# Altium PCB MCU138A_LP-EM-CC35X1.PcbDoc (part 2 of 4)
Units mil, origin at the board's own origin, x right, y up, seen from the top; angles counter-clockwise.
Board outline 2309.44 x 2672.36 mil, 4 copper layers (Top Layer, L02_GND, L03_PWR, Bottom Layer), stack 60 mil thick; 235 components, 167 nets, 678 pads, 887 vias.
Unrouted connection lines stored in the file: 19.
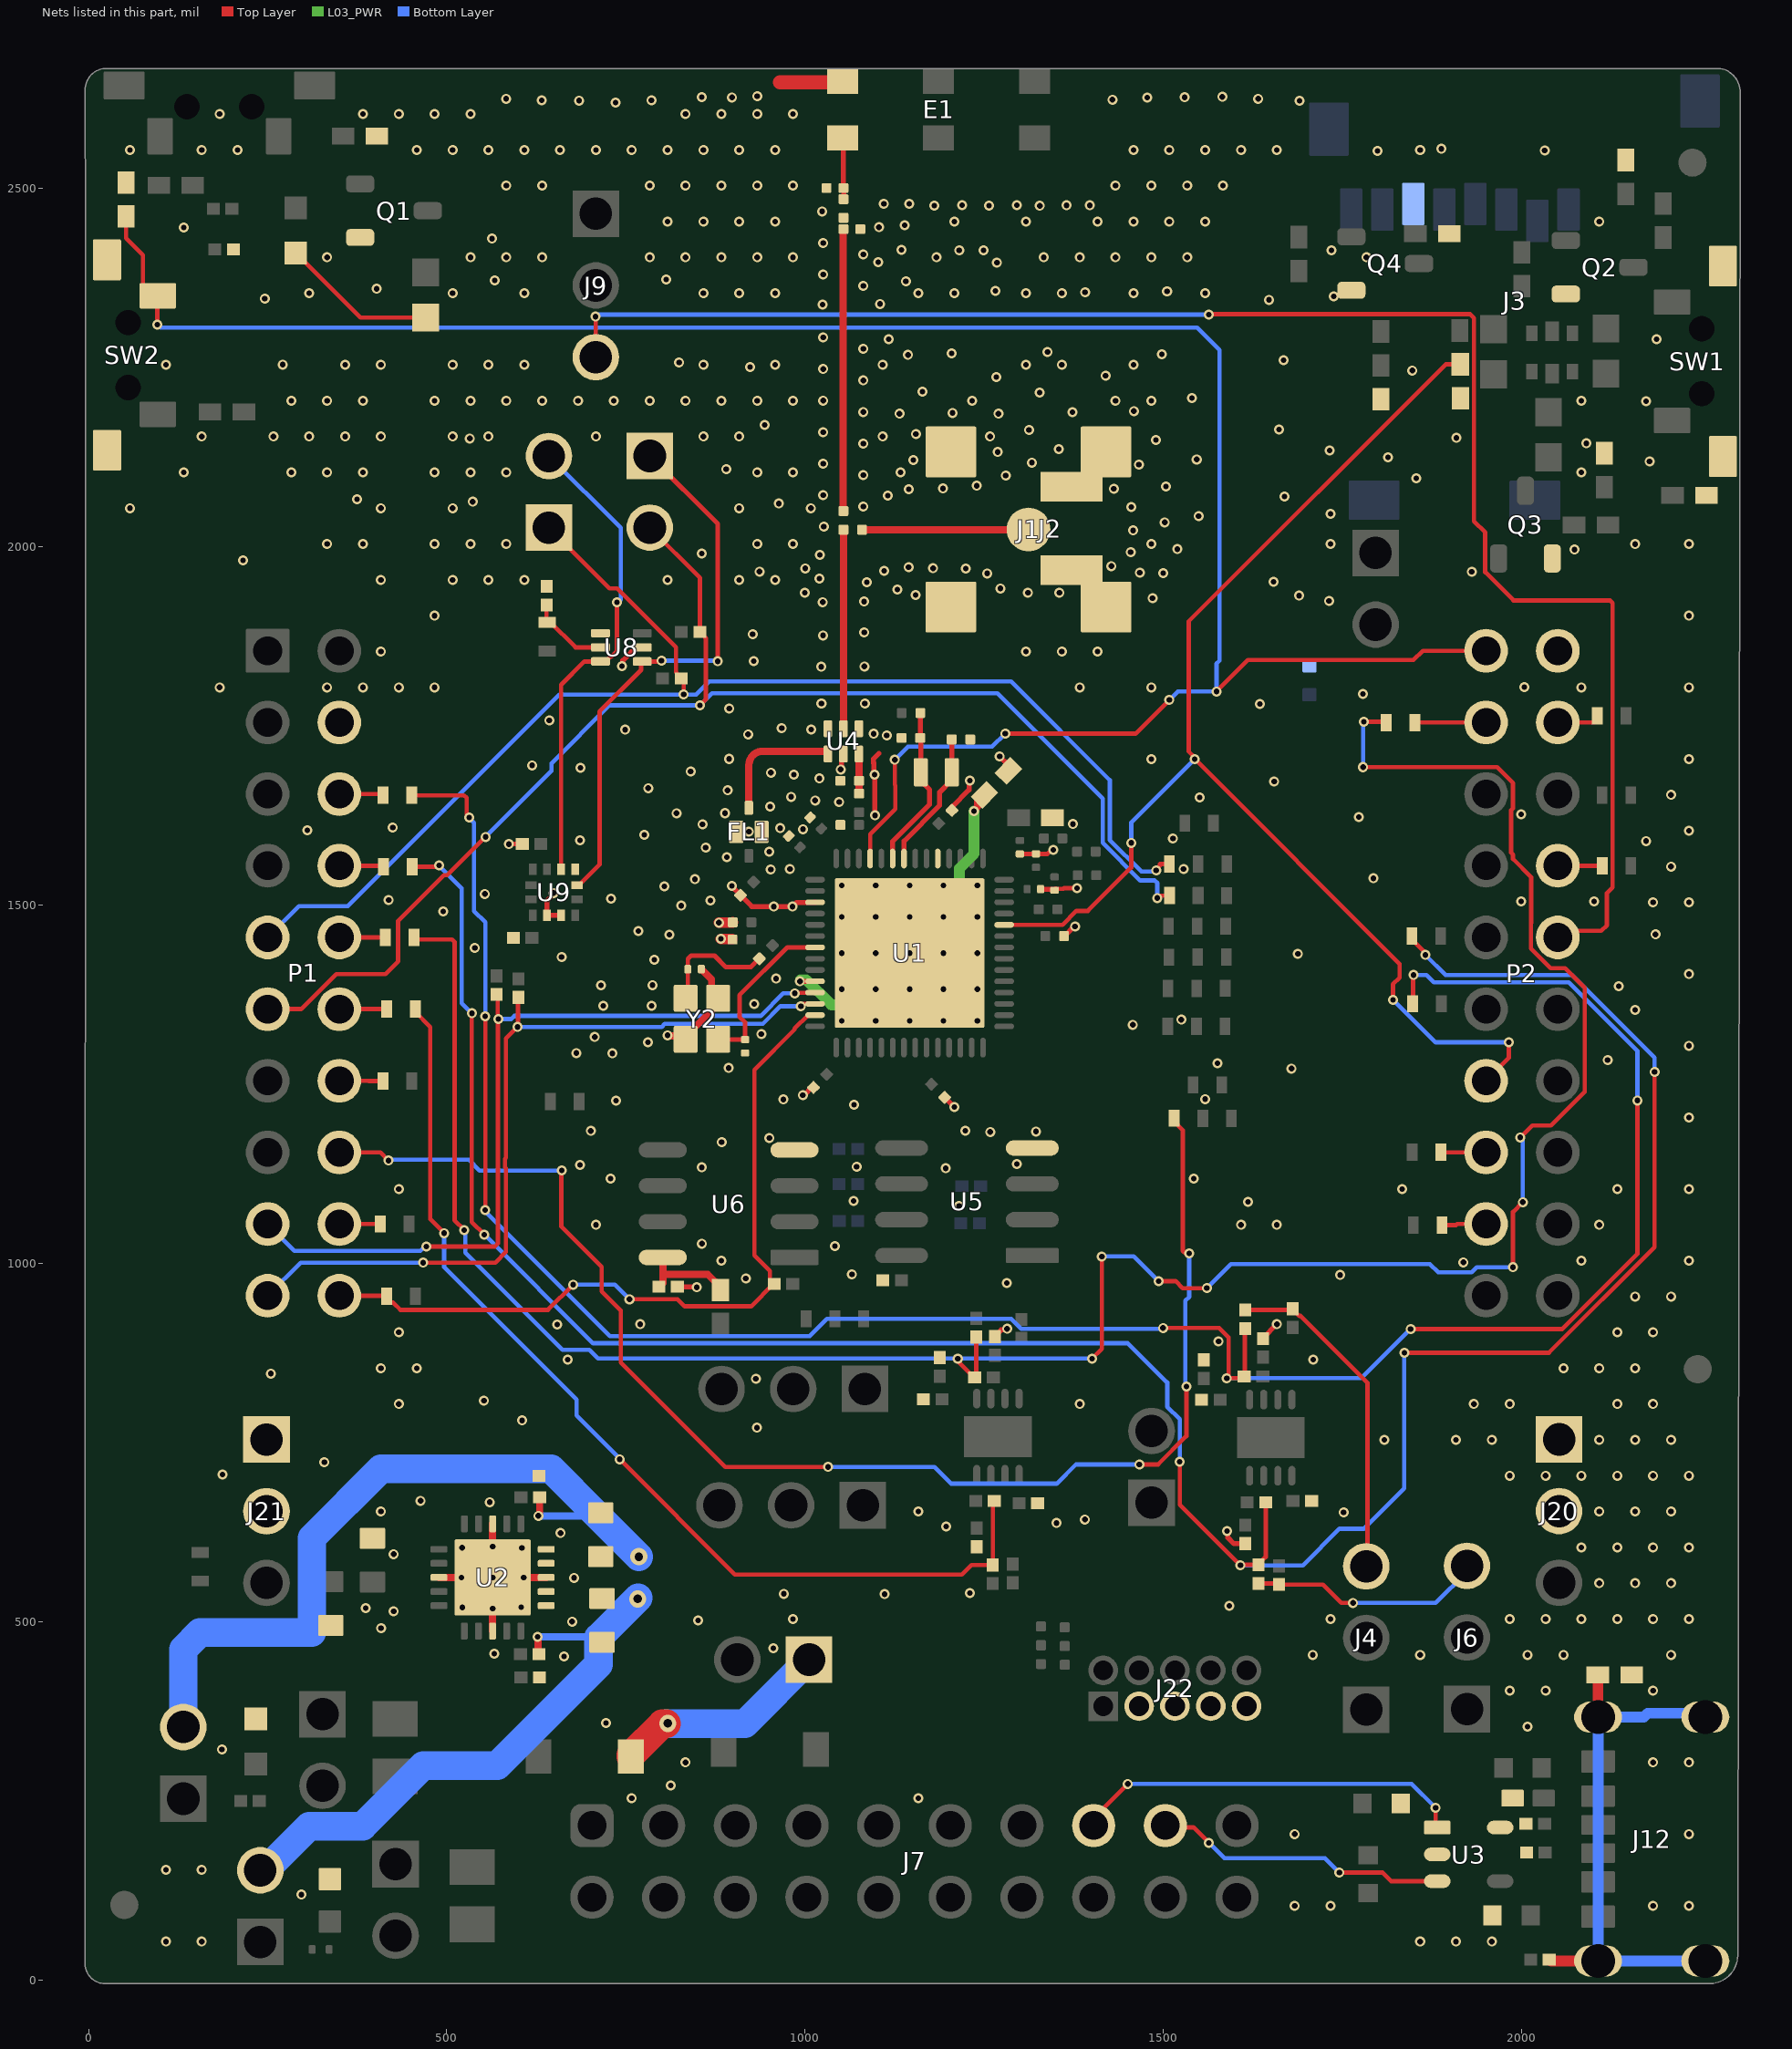
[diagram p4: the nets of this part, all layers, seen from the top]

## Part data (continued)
D1 D8: library part CMP-0028547-1, "Diode, Schottky, 30 V, 1 A, SOD-123", Manufacturer="ON Semiconductor", Supplier Part Number 1=MBR130T1GOSCT-ND, Value1=1A, Value2=0.47V
D2: "LED, Yellow, SMD", Alternate Manufacturer=Everlight, Alternate PartNumber=19-217/Y5C-AM1N1VY/3T, Color=yellow, Manufacturer="Wurth Elektronik", PartNumber=150060YS75000, Supplier Part Number 1=732-4981-1-ND, Value1=W, Value2=2V
D4: "LED, Rgb, SMD", Alternate Manufacturer=Everlight, Alternate PartNumber=19-337-R6GHBHC-C02-2T, Color=RGB, PartNumber=EAST1616RGBA8, Value1=W, Value2=3.7V
D5: library part CMP-0074747-2, "Diode, TVS, Bi, 5 V, SOD-523F", Manufacturer="ON Semiconductor", Value1=50W
D9: "LED, Green, SMD", Alternate Manufacturer=Everlight, Alternate PartNumber=19-217/GHC-YR1S2/3T, Color=Green, Manufacturer="Wurth Elektronik", PartNumber=150060GS75000, Supplier Part Number 1=732-4971-1-ND, Value1=W, Value2=3.2V
D10: library part CMP-0092006-1, "Red 630nm LED Indication - Discrete 1.5V 0603 (1608 Metric)", Color=Red, Digikey Part Number=2679-CTL0603FRD1TTR-ND, Forward Current=20mA, Manufacturer=Venkel, Operating Temperature Range="-40°C to +85°C", Power_TotalModule=60mW
E1: library part CMP-0001857-1, "WLAN ANTENNA 802.11, SMD", Alternate Manufacturer=----, Manufacturer=Ethertronics
FB1 FB2 FB3 FB4: library part CMP-0686-00587-3, "Chip Ferrite Bead, 0603, 470Ω @ 100MHz, 0.2Ω, 25%, 1A", Case Code (Imperial)=0603, Case Code (Metric)=1608, Current Rating=1A, DC Resistance (DCR)=200mR, Max Operating Temperature=125°C, Min Operating Temperature=-55°C, Package Quantity=1, Test Frequency=100MHz, Tolerance=25%
FID1 FID2 FID3: library part CMP-0077181-1, "Fiducial mark.  There is nothing to buy or mount.", Manufacturer=N/A
FL1: library part CMP-0091509-1, "2.45GHz Center Frequency Band Pass RF Filter (Radio Frequency) 100MHz Bandwidth 1.8dB 0603 (1608 Metric), 3 PC Pad", Digikey Part Number=445-175610-1-ND, Frequency_Fixed=2.45GHz, Manufacturer=TDK, Mouser Part Number=810-DEA162450BT1295A, Operating Temperature Range="-40°C to +85°C"
J1: library part CMP-0089646-1, "SMA Connector Jack, Female Socket 50Ohm Surface Mount Solder", Dielectric Material=PTFE, Digikey Part Number=931-1182-ND, Frequency_Fixed=0-12.4GHz, Manufacturer="Taoglas Limited", Mouser Part Number=960-PCB.SMAFST.J.BHT, Operating Temperature Range="-40°C to +85°C", Voltage_V=335V
J2: library part CMP-0075320-1, "Receptacle, Ultra Miniature Coaxial, Male Pin, 50 ohm, SMT", Alternate Manufacturer=----, Color=Beige, Manufacturer="Hirose Electric Co. Ltd.", Supplier Part Number 1=H122041-ND
J3: library part CMP-0078832-1, "MicroSD Card Connector, R/A, Gold, SMT", Color=Black, Current_A=5dA, Manufacturer="Wurth Elektronik", Supplier Part Number 1=732-3819-1-ND, Voltage_V=100V
J4 J6 J9 J10 J11 J20 J21: "Header, 2.54 mm, 3x1, Gold, TH", Alternate Manufacturer=----, Manufacturer="Wurth Elektronik", PartNumber=61300311121, Supplier Part Number 1=732-5316-ND
J5 J8 J13 J14 J15 J16 J17 J18: library part CMP-0054794-1, "Header, 2.54 mm, 2x1, Gold, TH", Manufacturer="Wurth Elektronik", Supplier Part Number 1=732-5315-ND
J7: library part CMP-0074634-1, "Receptacle, 2.54mm, 10x2, Gold, R/A, TH", Color=Black, Current_A=3A, Manufacturer="Sullins Connector Solutions", Supplier Part Number 1=S9205-ND, Voltage_V=1kV
J12: library part CMP-0094557-1, "24 (6+18 Dummy) Position USB-C (USB TYPE-C) USB 2.0 Receptacle Connector", Current_A=3A, Digikey Part Number=2073-USB4125-GF-A-0190CT-ND, Manufacturer=GCT, Mouser Part Number=640-USB4125-GF-A-190, Operating Temperature Range="-30°C to +85°C", Voltage_V=20V
J19: "Header, 2.54 mm, 2x1, Gold, TH", Alternate Manufacturer=----, Manufacturer="Wurth Elektronik", PartNumber=61300211121, Supplier Part Number 1=732-5315-ND
J22: "Header, 1.27 mm, 5x2, Gold, TH", Alternate Manufacturer=----, Color=Black, Manufacturer=Samtec, PartNumber=FTSH-105-01-F-D-K, Supplier Part Number 1=FTSH-105-01-F-D-K-ND
L1 L2: library part CMP-0090712-1, "3.9nH Unshielded Thick Film Inductor 500mA 170mOhm Max 0201 (0603 Metric)", Digikey Part Number=490-13933-1-ND, Manufacturer=Murata, Mouser Part Number=81-LQP03HQ3N9B02D, Operating Temperature Range="-55°C to +125°C", Self Resonant Frequency=7GHz, Test Frequency=500MHz, Tolerance_%=0.1nH
LBL1: library part CMP-0003625-1, "Thermal Transfer Printable Labels, 0.650\" W x 0.200\" H - 10,000 per roll", Manufacturer=Brady, Supplier Part Number 1=97C5133
LOGO1: library part CMP-0074844-1
Logo2 Logo8: library part CMP-0074838-1, "Texas Instrument Corporate Signature"
Logo3: library part CMP-0074847-1, "FCC_disclaimer"
Logo4: library part CMP-0074769-1
Logo5: library part CMP-0074840-1, "ESD Susceptible Symbol"
Logo7: library part CMP-0074846-1, "LaunchPad Rocket logo"
P1: library part CMP-0003837-2, "Receptacle, 2.54mm, 10x2, Tin, TH", Alternate Manufacturer="Major League Electronics", Alternate PartNumber=CRD-081413-A-G, Manufacturer=Samtec, Supplier Part Number 1=SAM1204-10-ND
P2: library part CMP-0078266-2, "Receptacle, 2.54mm, 10x2, Tin, TH", Alternate Manufacturer="Major League Electronics", Alternate PartNumber=CRD-081413-A-G, Manufacturer=Samtec, Supplier Part Number 1=SAM1204-10-ND
Q1 Q2 Q3 Q4: "MOSFET, N-CH, 50 V, 0.22 A, SOT-23", Alternate Manufacturer=ON, Alternate PartNumber=BSS138LT1G, Manufacturer="Fairchild Semiconductor", PartNumber=BSS138, Supplier Part Number 1=BSS138CT-ND, Value2="1.7 nC"
R1 R2 R3 R4: library part CMP-0078669-1, "RES, 10.0 k, 1%, 0.063 W, 0402", Manufacturer="Yageo America", Power_W=63mW, Supplier Part Number 1=311-10.0KLRCT-ND, TempCo="100 ppm/C", Tolerance_%=1%, Value2=0.063W, Value_Code=10k0, ValueDisplayed=10k
R5 R27 R41 R44 R50 R52 R56 R57 R58 R59 R60 R70 R71 R72 R73 R74 R75 R78 R79 R80 R81 R95 R96 R97 R98 R104 R105 R106 R107 R108: library part CMP-0027008-4, "RES, 0, 5%, 0.05 W, 0201", Manufacturer=Vishay-Dale, Power_W=50mW, Supplier Part Number 1=72M6743, TempCo=ppm/C, Tolerance_%=5%, Value2=0.05W, Value_Code=0000, ValueDisplayed=0
R6 R7 R9 R10 R11 R12 R13 R14 R15 R16 R17 R18 R19 R20 R21 R22 R23 R24 R25 R26 R28 R29 R30 R31 R32 R33 R34 R42 R43 R46 R61 R62 R66 R67 R82 R87 R88 R91 R99: "RES, 0, 5%, 0.063 W, 0402", Alternate Manufacturer=YAGEO, Alternate PartNumber=RC0402JR-070RL, Manufacturer=Panasonic, PartNumber=ERJ-2GE0R00X, Power_W=63mW, Supplier Part Number 1=P0.0JCT-ND, TempCo="600 ppm/C", Tolerance_%=5%, Value2=0.063W, Value_Code=0000, ValueDisplayed=0
R8 R83: "RES, 1.0 k, 5%, 0.063 W, AEC-Q200 Grade 0, 0402", Alternate Manufacturer=YAGEO, Alternate PartNumber=RC0402JR-071KL, Manufacturer=Vishay-Dale, PartNumber=CRCW04021K00JNED, Power_W=63mW, Supplier Part Number 1=541-1.0KJCT-ND, TempCo="200 ppm/C", Tolerance_%=5%, Value2=0.063W, Value_Code=1k00, ValueDisplayed=1.0k
R35: "RES, 750, 5%, 0.1 W, AEC-Q200 Grade 0, 0603", Alternate Manufacturer=YAGEO, Alternate PartNumber=RC0603JR-07750RL, Manufacturer=Vishay-Dale, PartNumber=CRCW0603750RJNEA, Power_W=100mW, Supplier Part Number 1=541-750GCT-ND, TempCo="200 ppm/C", Tolerance_%=5%, Value2=0.1W, Value_Code=750R, ValueDisplayed=750
R36: "RES, 100, 1%, 0.1 W, 0402", Alternate Manufacturer=----, Manufacturer=Panasonic, PartNumber=ERJ-2RKF1000X, Power_W=100mW, Supplier Part Number 1=P100LCT-ND, TempCo="100 ppm/C", Tolerance_%=1%, Value2=0.1W, Value_Code=100R, ValueDisplayed=100
R37: library part CMP-0027186-1, "RES, 10 k, 5%, 0.05 W, 0201", Manufacturer="Yageo America", Power_W=50mW, Supplier Part Number 1=603-RC0201JR-7D10KL, TempCo="200 ppm/C", Tolerance_%=5%, Value2=0.05W, Value_Code=10k0, ValueDisplayed=10k
R38 R89 R90: "RES, 10 k, 5%, 0.063 W, AEC-Q200 Grade 0, 0402", Alternate Manufacturer=YAGEO, Alternate PartNumber=RC0402JR-0710KL, Manufacturer=Vishay-Dale, PartNumber=CRCW040210K0JNED, Power_W=63mW, Supplier Part Number 1=541-10KJCT-ND, TempCo="200 ppm/C", Tolerance_%=5%, Value2=0.063W, Value_Code=10k0, ValueDisplayed=10k
R39: library part CMP-0027612-1, "RES, 33.2 k, 1%, 0.05 W, 0201", Manufacturer="Yageo America", Power_W=50mW, Supplier Part Number 1=YAG2607CT-ND, TempCo="200 ppm/C", Tolerance_%=1%, Value2=0.05W, Value_Code=33k2, ValueDisplayed=33.2k
R40: library part CMP-0027303-2, "RES, 10.7 k, 1%, 0.05 W, 0201", Manufacturer="Yageo America", Power_W=50mW, Supplier Part Number 1=311-10.7KMCT-ND, TempCo="200 ppm/C", Tolerance_%=1%, Value2=0.05W, Value_Code=10k7, ValueDisplayed=10.7k
R45: library part CMP-0027219-1, "RES, 2.0 k, 5%, 0.05 W, 0201", Manufacturer="Yageo America", Power_W=50mW, Supplier Part Number 1=603-RC0201JR-7D2KL, TempCo="200 ppm/C", Tolerance_%=5%, Value2=0.05W, Value_Code=2k00, ValueDisplayed=2.0k
R47 R48: library part CMP-0027789-1, "RES, 5.10 k, 1%, 0.05 W, 0201", Manufacturer="Yageo America", Power_W=50mW, Supplier Part Number 1=YAG2741CT-ND, TempCo="200 ppm/C", Tolerance_%=1%, Value2=0.05W, Value_Code=5k10, ValueDisplayed=5.10k
R49: library part CMP-0027957-1, "RES, 13.7 k, 1%, 0.05 W, 0201", Manufacturer="Yageo America", Power_W=50mW, Supplier Part Number 1=603-RC0201FR-7D13K7L, TempCo="200 ppm/C", Tolerance_%=1%, Value2=0.05W, Value_Code=13k7, ValueDisplayed=13.7k
R51: library part CMP-0027024-1, "RES, 11 k, 5%, 0.05 W, 0201", Manufacturer="Yageo America", Power_W=50mW, Supplier Part Number 1=311-11KNCT-ND, TempCo="200 ppm/C", Tolerance_%=5%, Value2=0.05W, Value_Code=11k0, ValueDisplayed=11k
R53: library part CMP-0097243-1, "49.9 Ohms ±1% 0.05W, 1/20W Chip Resistor 0201 (0603 Metric) Automotive AEC-Q200 Thick Film", Digikey Part Number=P123049CT-ND, Manufacturer="Panasonic Electronic Components", Mouser Part Number=667-ERJ-1GNF49R9C, Operating Temperature Range="-55°C to +125°C", Power_W=50mW, TempCo=200ppm/°C, Tolerance_%=1%
R54: library part CMP-0027960-1, "RES, 150, 1%, 0.05 W, 0201", Manufacturer="Yageo America", Power_W=50mW, Supplier Part Number 1=603-RC0201FR-7D150RL, TempCo="200 ppm/C", Tolerance_%=1%, Value2=0.05W, Value_Code=150R, ValueDisplayed=150
R55: library part CMP-0026822-3, "RES, 0, 5%, 0.063 W, AEC-Q200 Grade 0, 0402", Manufacturer=Vishay-Dale, Power_W=63mW, Supplier Part Number 1=541-0.0JCT-ND, TempCo="200 ppm/C", Tolerance_%=5%, Value2=0.063W, Value_Code=0000, ValueDisplayed=0
R63 R64: "RES, 0.1, 1%, 0.25 W, 0805", Alternate Manufacturer=----, Manufacturer=Bourns, PartNumber=CRM0805-FX-R100ELF, Power_W=250mW, Supplier Part Number 1=652-CRM0805FXR100ELF, TempCo="150 ppm/C", Tolerance_%=1%, Value2=0.25W, Value_Code=R100, ValueDisplayed=0.1
R65: library part CMP-0095637-1, "510 kOhms ±5% 0.1W, 1/10W Chip Resistor 0402 (1005 Metric) Automotive AEC-Q200 Thick Film", Digikey Part Number=P510KJCT-ND, Manufacturer=Panasonic, Mouser Part Number=667-ERJ-2GEJ514X, Operating Temperature Range="-55°C to +155°C", Power_W=100mW, TempCo=200ppm/°C, Tolerance_%=5%
R68 R69 R76 R77: library part CMP-0028132-1, "RES, 100 k, 0.5%, 0.05 W, 0201", Manufacturer="Yageo America", Power_W=50mW, Supplier Part Number 1=RC0201DR-07100KL-ND, TempCo="200 ppm/C", Tolerance_%=0.5%, Value2=0.05W, Value_Code=100k
R84 R85 R86: "RES, 750, 5%, 0.1 W, 0603", Alternate Manufacturer=----, Manufacturer="Yageo America", PartNumber=RC0603JR-07750RL, Power_W=100mW, Supplier Part Number 1=311-750GRCT-ND, TempCo="100 ppm/C", Tolerance_%=5%, Value2=0.1W, Value_Code=750R, ValueDisplayed=750
R92 R93 R94: "RES, 100 k, 5%, 0.063 W, AEC-Q200 Grade 0, 0402", Alternate Manufacturer=YAGEO, Alternate PartNumber=RC0402JR-07100KL, Manufacturer=Vishay-Dale, PartNumber=CRCW0402100KJNED, Power_W=63mW, Supplier Part Number 1=541-100KJCT-ND, TempCo="200 ppm/C", Tolerance_%=5%, Value2=0.063W, Value_Code=100k
R100 R101 R102 R103: library part CMP-0027564-1, "RES, 2.55 k, 1%, 0.05 W, 0201", Manufacturer="Yageo America", Power_W=50mW, Supplier Part Number 1=YAG2577CT-ND, TempCo="200 ppm/C", Tolerance_%=1%, Value2=0.05W, Value_Code=2k55, ValueDisplayed=2.55k
S1: library part CMP-0002328-1, "Switch, SPST, 0.05 A, 12 VDC, SMD", CurrentRating_mA=50A, Manufacturer=Diptronics
SH-J1 SH-J2 SH-J3 SH-J4 SH-J5 SH-J6 SH-J7 SH-J8 SH-J9 SH-J10 SH-J11 SH-J12 SH-J13 SH-J14: library part CMP-0003623-3, "Shunt, 100mil, Gold plated, Black", Alternate Manufacturer=3M, Alternate PartNumber=969102-0000-DA, Manufacturer=Samtec, PartNumber=SNT-100-BK-G, Supplier Part Number 1=SAM8858-ND
SW1 SW2: "Switch, SPST, 0.05 A, 12 VDC, SMD", Alternate Manufacturer=----, CurrentRating_mA=50A, Manufacturer=Diptronics, PartNumber=1188E-1K2-V-TR
U1: library part CMP-0121078-1, Manufacturer="Texas Instruments", Operating Temperature Range=to
U2: library part CMP-0073732-3, "Dual 1A Low-Noise (3.8μVRMS) LDO Voltage Regulator, RTJ0020D (WQFN-20)", Alternate Manufacturer="Texas Instruments", Alternate PartNumber=TPS7A8801RTJT, Operating Temperature Range="-40 to 125 C", Rating=Catalog
U3: library part CMP-0087170-1, "8KB I2C SER EEPROM TSOT 23", Manufacturer="ON Semiconductor"
U4: library part CMP-0091972-1, "Multilayer Diplexer For 2.4-2.5GHz W-LAN & Bluetooth / 5-7GHz W-LAN", Manufacturer=TDK, Operating Temperature Range="-40°C to +85°C"
U5: library part CMP-0120365-1, "FLASH - NOR Memory IC 64Mbit SPI - Quad I/O, QPI, DTR 133 MHz 6 ns 8-SOP", Digikey Part Number=706-IS25WJ032F-JNLE-ND, Frequency_Fixed=133MHz, Manufacturer=ISSI, Max Supply Voltage=2V, Min Supply Voltage=1.65V, Mouser Part Number=870-IS25WJ032F-JNLE, Nominal Supply Current=1.2-10mA, Operating Temperature Range="-40°C to +105°C", Part Number=IS25WJ032F-JNLE
U6: library part CMP-0121002-1, "DRAM IoT RAM 16Mb QSPI (x1,x4) SDR 144/84MHz, RBX, 1.8V, Ext. Temp., SOP8", Frequency_Fixed=144MHz, Manufacturer="AP Memory", Max Supply Voltage=1.98V, Min Supply Voltage=1.62V, Mouser Part Number=878-APS1604M-SQRX-SN, Nominal Supply Current=5-7mA, Operating Temperature Range="-40°C to +105°C"
U7 U10: library part CMP-0040617-1, "1.1 nV/rtHz Noise, Low Power, Precision Operational Amplifier, 4.5 to 36 V, -40 to 125 degC, 8-pin SON (DRG8), Green (RoHS & no Sb/Br)", Manufacturer="Texas Instruments", Rating=Catalog, Total Supply Voltage(Max)(+5V is 5, +/-5V is 10)=36, Total Supply Voltage(Min)(+5V is 5, +/-5V is 10)=4.5
U8: library part CMP-0092110-1, "Temperature Sensor With I 2C and SMBus Interface in Industry Standard LM75 Form Factor and Pinout", Manufacturer="Texas Instruments", Max Supply Voltage=5.5V, Min Supply Voltage=1.7V, Operating Supply Current=4-52uA, Operating Temperature Range="to +150°C"
U9: library part CMP-0004812-1, "14 Bit, Digital, Triaxial Acceleration Sensor with Intelligent On-Chip Motion-Triggered Interrupt Controller, 12LGA", Manufacturer="Bosch Solar Energy", Supplier Part Number 1=828-1033-1-ND
Y1: library part CMP-0001358-1, "Crystal Unit 1.6x1.0 Tuning Fork 32.768KHz", Frequency Stability=380ppm, Frequency Tolerance=20ppm, Frequency_Fixed=32.768kHz, Load Capacitance=7pF, Manufacturer="TAI-SAW Technology", Operating Temperature Range="-40°C to +125°C"
Y2: library part CMP-0123571-1, "Crystal Unit SMD 2.0x1.6 52.0MHz", Frequency Stability=-16/+18ppm, Frequency Tolerance=5ppm, Frequency_Fixed=52MHz, Load Capacitance=7pF, Manufacturer="TAI-SAW TECHNOLOGY", Operating Temperature Range="-40°C to +105°C"
ZZ1: library part CMP-0003616-3
ZZ2: library part CMP-0077236-1
ZZ3: library part CMP-0077237-1
ZZ4: library part CMP-0077238-1

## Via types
v1: diameter 14, hole 7.87, Top Layer to Bottom Layer, tented both sides, 816 vias
v2: diameter 19.68, hole 7.87, Top Layer to Bottom Layer, tented both sides, 25 vias
v3: diameter 14, hole 8, Top Layer to Bottom Layer, tented both sides, 19 vias
v4: diameter 24, hole 12, Top Layer to Bottom Layer, tented both sides, 14 vias
v5: diameter 19.68, hole 7.87, Top Layer to Bottom Layer, 13 vias

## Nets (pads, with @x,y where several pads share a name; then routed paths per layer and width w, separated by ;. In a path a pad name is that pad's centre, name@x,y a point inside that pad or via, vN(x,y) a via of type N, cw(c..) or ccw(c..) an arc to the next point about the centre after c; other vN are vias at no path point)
ADC2: P1.23 R7.2 | length 61.7
  Top Layer w6: P1.23@349.99,1654.89 409.3,1654.89 R7.2@411.02,1653.17
ADC3: P1.24 R10.2 | length 62.1
  Top Layer w6: P1.24@349.99,1554.89 410.2,1554.89 R10.2@411.54,1553.55
ADC4: P1.25 R12.2 | length 64.2
  Top Layer w6: P1.25@349.99,1454.89 413.98,1454.89 R12.2@414.15,1454.73
ADC5: P1.26 R15.2 | length 66.3
  Top Layer w6: P1.26@349.99,1354.89 416.01,1354.89 R15.2@416.19,1355.07
BoardID_SCA: J7.17 U3.3 | length 411.5
  Top Layer w6: J7.17@1502.5,215.64 1504.97,213.18 1541.62,213.18 v1(1563.3,191.5) ; v1(1745.32,149.98) 1805.63,149.98 1817.54,138.08 U3.3@1881.83,138.08
  Bottom Layer w6: v1(1563.3,191.5) 1584.82,169.98 1725.32,169.98 v1(1745.32,149.98)
BoardID_SCL: J7.15 U3.1 | length 549.5
  Top Layer w6: J7.15@1402.5,215.64 1402.5,226.09 v1(1450.14,273.74) ; v1(1879.53,240.42) 1879.53,215.18 U3.1@1881.83,212.88
  Bottom Layer w6: v1(1450.14,273.74) 1846.21,273.74 v1(1879.53,240.42)
COEX_GRANT: P2.40 R90.1 SW2.3 U1.53 | length 3188.8
  Top Layer w6: R90.1@52.45,2461.03 52.45,2430.73 76.07,2407.11 76.07,2364.87 90.79,2350.16 SW2.3@96.72,2350.16 96.18,2349.62 v1(96.18,2309.89) ; U1.53@1090.56,1564.97 1090.9,1565.3 1090.9,1599 1094.85,1602.96 1125.84,1633.94 1125.84,1666.79 1125.05,1667.58 v1(1125.05,1702.81) ; v1(1279.13,1739.24) 1461.07,1739.24 v1(1508.03,1786.2) ; v1(1573.92,1798.08) 1617.75,1841.9 1848.76,1841.9 1861.75,1854.89 P2.40@1949.99,1854.89
  Bottom Layer w6: v1(96.18,2309.89) 100.12,2305.95 1546.85,2305.95 1578.23,2274.58 1578.23,1841.08 1573.92,1836.77 v1(1573.92,1798.08) 1519.91,1798.08 v1(1508.03,1786.2) ; v1(1125.05,1702.81) 1143.26,1721.03 1260.91,1721.03 v1(1279.13,1739.24)
COEX_PRIOR: P2.39 R6.1 | length 99.6
  Top Layer w6: R6.1@1850.52,1754.59 1850.82,1754.89 P2.39@1949.99,1754.89
COEX_REQ: P2.19 R99.2 | length 61.5
  Top Layer w6: P2.19@2049.99,1754.89 2100.54,1754.89 2105.07,1759.43 R99.2@2105.07,1763.93
DCAN_TX: P2.32 R24.1 | length 62
  Top Layer w6: R24.1@1888.54,1053.55 1908.13,1053.55 1909.47,1054.89 P2.32@1949.99,1054.89
DIG_LDO_OUT: C23.2 U1.10 U1.47 | length 559.5
  Top Layer w7: v3@992.64,1393.71 U1.10@1013.79,1393.71
  Top Layer w10: v3(1235.58,1631.13) 1235.58,1632.21 1240.64,1637.27 1240.64,1648.14 1246.36,1653.86 C23.2@1250.11,1653.86
  L03_PWR w15: v3@993.78,1396.16 1001.02,1396.16 1036.4,1360.79 1202.44,1360.79 1215.24,1373.59 1215.24,1551.3 1235.58,1571.64 v3(1235.58,1631.13)
  other v3: 992.64,1393.61
Diplexer_A_IN: C11.1 C36.2 U4.6 | length 55.3
  Top Layer w10.25: U4.6@1074.94,1710.76 1075.03,1710.67 1075.03,1673.42 C36.2@1075.12,1673.33 C36.2@1075.12,1673.33 ; C36.2@1075.12,1673.33 C11.1@1075.15,1655.58 C11.1@1075.15,1655.58
Diplexer_BG_IN: FL1.3 U4.4 | length 182.5
  Top Layer w10.25: FL1.3@921.39,1635.72 921.39,1695.37 cw(c940.66,1695.37) 940.66,1714.64 1027.76,1714.64 U4.4@1031.63,1710.76
Diplexer_out: C8.1 C9.2 U4.2 | length 277.7
  Top Layer w10.25: U4.2@1053.29,1746.19 1053.29,2022.01 1053.38,2022.09 C9.2@1053.38,2023.85
GND: C1.2 C2.1 C3.1 C4.1 C5.1 C6.2 C7.2 C10.2 C12.2 C13.1 C14.1 C15.2 C16.2 C17.1 C18.2 C19.2 C20.1 C21.2 C22.2 C23.1 C24.2 C25.2 C26.1 C27.2 C28.1 C29.1 C30.1 C31.2 C32.2 C33.2 C34.2 C35.2 C36.1 C38.2 C40.2 C41.2 C42.2 D5.2 D9.1 D10.1 E1.1 E1.6 FB2.2 FB4.2 FL1.2 FL1.4 J1.2 J1.3 J1.4 J1.5 J2.2@1371.62,2083.61 J2.3@1371.62,1967.47 J3.6 J20.1 J20.2 J21.1 J21.2 J22.3 J22.5 J22.7 J22.9 L1.1 L2.1 L2.2 P1.22 P2.20 Q1.2 Q2.2 Q3.2 Q4.2 R3.2 R4.2 R36.2 R40.1 R47.1 R48.2 R51.1 R65.1 R68.1 R69.1 R76.1 R77.1 R80.1 R81.1 R89.2 R90.2 R92.2 R93.2 R94.2 SW1.1 SW1.2 SW2.1 SW2.2 U1.3 U1.57 U2.3 U2.8 U2.13 U2.18 U2.21 U3.2 U3.5 U4.1 U4.3 U4.5 U5.4 U6.4 U8.2 U8.4 U9.1 U9.8 U9.9 Y2.2 Y2.4 | length 1203.8
  Top Layer w6: v1(586.76,1585.12) 586.86,1585.22 C16.2@605.26,1585.22 ; C32.2@1299.55,1571.34 1299.61,1571.4 1321.96,1571.4 C12.2@1322.02,1571.46 1338.3,1571.46 1343.88,1577.04 v1(1346.05,1577.04) ; C31.2@1349.84,1522.6 1360.12,1522.6 1361.23,1523.72 v1(1379.25,1523.72)
  Top Layer w7: v1(648.92,1516.86) 648.92,1514.97 639.66,1505.71 U9.8@639.66,1485.84 U9.9@659.34,1485.84 ; v1(744.15,1833.57) 745.49,1834.91 745.49,1841.35 757.49,1853.35 759.08,1853.35 765.36,1859.63 U8.2@772.64,1859.63 ; C38.2@821.73,967.29 822.05,966.97 848.39,966.97 v1(848.71,966.66) ; v1@901.25,1522.2 925.44,1498 v3(956.29,1498) v3(982.28,1498) 988.05,1503.77 1013.62,1503.77 U1.3@1013.79,1503.94 ; v1(996.69,1234.93) 998.58,1234.93 1009.13,1245.48 C35.2@1011.62,1245.48 ; v3(1049.57,1689.25) 1050.91,1690.59 1050.91,1708.38 U4.5@1053.29,1710.76 ; E1.1@1052.13,2570.57 cw(c1049.15,2567.6) 1053.36,2567.6 L2.2@1053.36,2500.57 ; C10.2@1053.85,2488.35 L2.2@1053.85,2500.57 ; v3(1097.31,1625.21) 1097.11,1625.41 1097.11,1681.96 1095.58,1683.49 1095.58,1698.03 1095.26,1698.35 1095.26,1704.15 1102.68,1711.57 ; C33.2@1194.57,1231.63 v1(1208.01,1218.23) ; C22.2@1204.73,1632.29 1204.73,1637 1228.5,1660.76 1228.5,1672.46 v1(1229.84,1673.8) ; R68.1@1264.71,897.81 1264.71,898.6 1273.52,907.41 1280.39,907.41 v1(1281.72,908.75) ; v1(1271.4,1707.61) 1283.52,1695.48 C23.1@1283.52,1687.27 C23.1@1292.71,1687.27 ; C15.2@1327.67,1521.53 C15.2@1328.41,1522.27 1349.51,1522.27 C31.2@1349.84,1522.6 ; C34.2@1361.08,1456.88 1361.87,1456.88 1375.13,1470.14 v1(1376.42,1470.14) ; v1(1588.42,626.56) 1589.76,625.22 1589.76,617.37 1598.13,609 R77.1@1613.95,608.98 ; R69.1@1638.56,895.15 1638.56,895.93 1657.76,915.13 v1(1658.17,915.13)
  Top Layer w10: U2.3@489.08,561.81 v5(520.58,561.81) ; U2.8@563.88,487 v5(563.88,518.5) ; v5(563.88,605.11) U2.18@563.88,636.61 ; v5(607.19,561.81) U2.13@638.69,561.81 ; v3@808.33,1317.69 832.7,1317.69 836.27,1314.12 836.27,1319.67 881.54,1364.94 Y2.4@881.54,1368.82 ; C20.1@855.12,1409.68 855.95,1409.68 869.38,1396.25 869.38,1379.01 Y2.4@878.5,1369.89 ; J2.3@1363.66,1959.35 J2.3@1371.1,1966.79
  Top Layer w15: v3(879.55,1475.55) 898.55,1475.55 C24.2@898.94,1475.94 ; v3@882.51,1452.75 C25.2@897.89,1452.75
  Top Layer w20: 965.07,2648.17 E1.6@1045.57,2648.17
  other v1: 108.01,53.8 158.01,53.8 1858.01,53.8 1908.01,53.8 1958.01,53.8 1683.01,103.8 1733.01,103.8 2183.01,103.8 2233.01,103.8 297.26,119.28 108.01,153.8 158.01,153.8 1683.01,203.8 2233.01,203.8 758.01,253.8 1158.01,253.8 812.52,271.45 833.01,303.8 2183.01,303.8 2233.01,303.8 186.15,321.7 2008.01,353.8 721.88,358.83 1983.01,403.8 2033.01,403.8 2183.01,403.8 663.49,451.53 1708.01,453.8 1858.01,453.8 2008.01,453.8 2058.01,453.8 2208.01,453.8 566.14,455.57 955.47,462.97 408.21,490.89 674.69,500.2 850.7,501.72 983.01,503.8 1733.01,503.8 1983.01,503.8 2033.01,503.8 2083.01,503.8 2133.01,503.8 2183.01,503.8 2233.01,503.8 425.86,514.46 386.84,519.01 1591.86,522.23 970.32,539 1110.69,538.55 1229.91,539.9 2108.01,553.8 2158.01,553.8 2208.01,553.8 677.7,561.35 425.86,594.4 2083.01,603.8 2133.01,603.8 2183.01,603.8 2233.01,603.8 658.75,623.8 1196.73,632.87 1350.83,637.77 1390.35,642.7 1751.23,652.85 408.01,653.8 1158.01,653.8 2108.01,653.8 2158.01,653.8 2208.01,653.8 559.7,666.87 463.45,668.87 1983.01,703.8 2033.01,703.8 2083.01,703.8 2133.01,703.8 2183.01,703.8 2233.01,703.8 187.13,705.35 329.11,722.72 1808.01,753.8 1908.01,753.8 1958.01,753.8 2108.01,753.8 2158.01,753.8 2208.01,753.8 932.53,770.69 604.9,780.94 433.01,803.8 1383.01,803.8 1933.01,803.8 1983.01,803.8 2133.01,803.8 2183.01,803.8 551.78,808.52 931.18,839.08 254.55,846.31 408.01,853.8 458.01,853.8 2058.01,853.8 2108.01,853.8 2158.01,853.8 668.47,865.63 1708.82,865.63 1576.79,891.09 433.01,903.8 2133.01,903.8 2183.01,903.8 654.04,914.66 769.67,915.11 2158.01,953.8 2208.01,953.8 1281.3,972.76 917.15,979.2 1746.2,983.92 1065.21,984.64 1918.43,1001.6 883.01,1003.8 2083.01,1003.8 2233.01,1003.8 1041.53,1024.11 855.92,1027.64 708.01,1053.8 1608.01,1053.8 1658.01,1053.8 2108.01,1053.8 1214.81,1080.04 1617.85,1085.8 1067.34,1086.99 433.01,1103.8 1833.01,1103.8 2133.01,1103.8 2233.01,1103.8 728.46,1118.3 1542.04,1118.36 1196.06,1132.72 855.64,1134.06 1071.7,1134.78 685.93,1137.49 1295.3,1138.88 883.4,1169.17 950.15,1175.13 1258.1,1183.56 1322,1184.2 700.78,1184.95 1223.44,1185.25 2233.01,1203.8 1068.03,1221.34 735.89,1227.14 969.41,1228.77 1558.04,1229.3 1678.58,1271.97 893.23,1272.7 1575.11,1279.44 2119.54,1283.72 731.12,1293.02 680.57,1293.6 2233.01,1303.8 780.53,1308.53 706.42,1316 938.76,1320.18 1457.09,1332.98 1524.65,1340.15 2158.01,1353.8 718.43,1359.42 785.58,1359.42 928.93,1362.06 2134.88,1386.73 714.92,1388.18 786.81,1388.36 959.35,1397.4 2233.01,1403.8 789.34,1423.71 660.07,1427.47 1687.42,1432.13 539.1,1440.18 810.39,1458.69 2186.39,1459.05 767.12,1463.68 495.08,1491.19 826.86,1499.15 2183.01,1503.8 2233.01,1503.8 1999,1505.08 2100.91,1505.08 418.84,1507.27 729.17,1508.79 553.16,1515.57 803.67,1526.19 897.55,1526.82 846.03,1536.07 1792.67,1537.38 952.01,1549.78 978.67,1550.18 1527.83,1550.45 2208.01,1553.8 890.71,1566.92 949.88,1574.54 861.18,1580.06 2173.24,1589.46 685.66,1590.33 1513.11,1592.77 775.52,1598.02 921.47,1602.51 305.26,1604.25 2233.01,1603.8 996.85,1605.99 965.04,1607.28 424.54,1608.4 856.67,1612.5 1373.74,1613.01 1772.38,1622.98 1999,1626.71 820.48,1628.18 887.98,1628.27 951.3,1637.5 1047.38,1644.01 1013.85,1645.96 1550.55,1650.26 980.19,1651.06 2208.01,1653.8 891.66,1660.11 780.97,1663.15 1654.39,1672.61 1019.88,1676.64 984.22,1682.15 952.11,1684.79 840.2,1686.29 686.45,1691.38 619.03,1695.01 893.71,1703.97 1483.01,1703.8 2233.01,1703.8 1113.67,1736.92 920.27,1738.22 1095.64,1739.02 748.69,1744.8 1008.26,1744.88 967.25,1746.93 642.89,1757.77 894.14,1774.19 1022.68,1781.28 1083.24,1781.11 1634.54,1780.44 1778.23,1794.78 183.01,1803.8 333.01,1803.8 383.01,1803.8 433.01,1803.8 483.01,1803.8 1383.01,1803.8 1483.01,1803.8 2003.38,1804.24 2083.01,1803.8 2233.01,1803.8 1022.16,1832.57 1082.57,1833.05 928.04,1840.63 408.01,1853.8 1308.01,1853.8 1358.01,1853.8 1408.01,1853.8 1024.83,1876.35 926.69,1877.92 1082.48,1880.39 483.01,1903.8 2233.01,1903.8 1024.51,1922.71 1081.97,1923.55 1730.88,1924.33 1484.61,1928.08 1689.07,1931.79 1153.96,1932.71 999.33,1935.81 1310.81,1935.78 1354.74,1935.78 1128.41,1940.37 1272.49,1941.91 1085.83,1950.57 1653.59,1951.3 408.01,1953.8 508.01,1953.8 558.01,1953.8 608.01,1953.8 808.01,1953.8 908.01,1953.8 958.01,1953.8 1019.71,1955.76 1254.1,1962.86 1499.37,1963.16 1466.75,1964.03 936.18,1965.38 1929.97,1965.32 1110.02,1966.43 999.97,1969.86 1178.48,1970.01 1223.95,1969.5 1144.25,1971.54 1427.29,1973.07 215.49,1980.97 1020.65,1988.66 855.5,1990.47 1454.14,1992.3 2073.52,1996 1519.28,1996.74 333.01,2003.8 383.01,2003.8 483.01,2003.8 533.01,2003.8 583.01,2003.8 933.01,2003.8 983.01,2003.8 1483.01,2003.8 1733.01,2003.8 2157.9,2003.67 2233.01,2003.8 1457.65,2022.75 1025.9,2027.96 1501.63,2034.12 1548.87,2042.94 1732.89,2045.91 58.01,2053.8 408.01,2053.8 508.01,2053.8 908.01,2053.8 1008.01,2053.8 1081.17,2056.06 1455.01,2055.37 963.3,2060.3 536.05,2062.87 374.81,2066.4 1668.77,2069.95 1025.14,2071.95 1115.36,2071.53 1144.67,2080.27 1192.14,2081.25 1430.51,2080.98 1503.19,2083.95 1239.12,2085.16 1852.57,2095.69 1081.1,2100.06 1279.74,2099.36 133.01,2103.8 283.01,2103.8 333.01,2103.8 383.01,2103.8 483.01,2103.8 533.01,2103.8 583.01,2103.8 933.01,2103.8 983.01,2103.8 1133.01,2103.8 2083.01,2103.8 889.79,2108.11 1465.53,2114.75 1025.14,2115.95 1316.44,2117.46 2178.05,2119.11 1151.03,2120.89 1546.27,2121.84 1813.08,2124.72 1268.48,2132.14 1731.8,2134.22 1353.64,2136.19 1081.1,2144.06 2089.72,2144.31 1489.17,2148.84 532.1,2151.15 1908.77,2151.89 158.01,2153.8 258.01,2153.8 308.01,2153.8 358.01,2153.8 408.01,2153.8 508.01,2153.8 558.01,2153.8 708.01,2153.8 858.01,2153.8 908.01,2153.8 1108.01,2153.8 1258.01,2153.8 1154.46,2157.1 1025.14,2159.95 1312.16,2162.85 1661.27,2163.52 943.63,2170.13 1131.52,2185.69 1269.6,2185.69 1205.75,2186.73 1081.1,2188.06 1372.9,2187.77 1458.55,2189.33 2173.44,2203.09 283.01,2203.8 333.01,2203.8 383.01,2203.8 483.01,2203.8 533.01,2203.8 583.01,2203.8 633.01,2203.8 683.01,2203.8 733.01,2203.8 783.01,2203.8 833.01,2203.8 883.01,2203.8 933.01,2203.8 983.01,2203.8 1025.14,2203.95 1233.01,2203.8 1433.01,2203.8 1483.01,2203.8 2083.01,2203.8 1539.52,2207.49 1327.22,2215.28 1163.57,2216.33 1081.1,2232.06 1266.61,2236.68 1419.09,2238.64 1847.09,2245.94 1025.14,2247.95 923.3,2250.81 108.01,2253.8 271.08,2254.2 358.01,2253.8 408.01,2253.8 508.01,2253.8 558.01,2253.8 608.01,2253.8 858.01,2253.8 958.01,2253.8 1108.01,2253.8 1308.01,2253.8 1358.01,2253.8 1458.01,2253.8 824.14,2257.19 1667.32,2260.4 1143.46,2267.71 1497.48,2268.75 1204.28,2269.76 1338.12,2271.86 1081.1,2276.06 1116.35,2289.68 2188,2289.46 1025.14,2291.95 1024.35,2338.02 1104.5,2338.79 1647.24,2344.59 246,2346.4 1737.41,2349.33 308.01,2353.8 508.01,2353.8 608.01,2353.8 858.01,2353.8 908.01,2353.8 958.01,2353.8 1158.01,2353.8 1208.01,2353.8 1308.01,2353.8 1358.01,2353.8 1458.01,2353.8 1558.01,2353.8 1390.5,2355.13 1265.44,2356.99 1504.92,2356.36 401.93,2359.96 1081.1,2364.06 1140.44,2370.31 566.68,2371.49 806.01,2372.84 1025.14,2379.95 1101.96,2397.3 1267.51,2396.47 333.01,2403.8 533.01,2403.8 583.01,2403.8 633.01,2403.8 783.01,2403.8 833.01,2403.8 883.01,2403.8 933.01,2403.8 983.01,2403.8 1183.01,2403.8 1333.01,2403.8 1383.01,2403.8 1433.01,2403.8 1483.01,2403.8 1533.01,2403.8 1783.01,2403.8 1081.1,2408.06 1214.86,2413.84 1248.83,2413.84 1734.17,2413.71 1134.43,2414.32 1025.14,2423.95 563.13,2429.94 133.07,2445.65 1102.9,2445.83 1138.64,2448.72 808.01,2453.8 858.01,2453.8 908.01,2453.8 958.01,2453.8 1208.01,2453.8 1308.01,2453.8 1408.01,2453.8 1458.01,2453.8 1508.01,2453.8 1558.01,2453.8 2108.01,2453.8 1023.83,2467.93 1180.22,2476.06 1256.38,2476.06 1327.32,2475.69 1218.87,2476.45 1295.42,2476.45 1364.68,2476.34 1397.16,2476.34 1109.79,2478.36 1145,2478.74 583.01,2503.8 633.01,2503.8 783.01,2503.8 833.01,2503.8 883.01,2503.8 933.01,2503.8 983.01,2503.8 1433.01,2503.8 1483.01,2503.8 1533.01,2503.8 1583.01,2503.8 1798.71,2552.3 2031.7,2552.88 58.01,2553.8 158.01,2553.8 208.01,2553.8 458.01,2553.8 508.01,2553.8 558.01,2553.8 608.01,2553.8 658.01,2553.8 708.01,2553.8 758.01,2553.8 808.01,2553.8 858.01,2553.8 908.01,2553.8 958.01,2553.8 1458.01,2553.8 1508.01,2553.8 1558.01,2553.8 1608.01,2553.8 1658.01,2553.8 1858.01,2553.8 1887.69,2555.22 183.01,2603.8 383.01,2603.8 433.01,2603.8 483.01,2603.8 533.01,2603.8 833.01,2603.8 883.01,2603.8 933.01,2603.8 983.01,2603.8 735.49,2619.78 632.22,2622.87 684.5,2622.61 785.45,2622.87 1689.76,2622.39 1428.65,2623.91 582.78,2625.18 1632.12,2625.18 897.98,2626.99 1477.05,2626.9 1529.31,2627.12 855.75,2627.5 1582,2627.76 933.01,2628.53
  other v2: 1051.19,1338.59 1098.43,1338.59 1145.68,1338.59 1192.92,1338.59 1240.16,1338.59 1051.19,1382.68 1098.43,1382.68 1145.68,1382.68 1192.92,1382.68 1240.16,1382.68 1051.19,1433.08 1098.43,1433.08 1145.68,1433.08 1192.92,1433.08 1240.16,1433.08 1051.19,1483.47 1098.43,1483.47 1145.68,1483.47 1192.92,1483.47 1240.16,1483.47 1051.19,1527.56 1098.43,1527.56 1145.68,1527.56 1192.92,1527.56 1240.16,1527.56
  other v3: 807.94,1318.41 882.29,1452.97 867.67,1506.52 1096.92,1682.15
  other v5: 521.81,520.02 603.63,520.44 563.88,561.81 521.41,603.24 604.79,602.95
GPT0: P2.33 R21.1 | length 63.3
  Top Layer w6: R21.1@1886.84,1155.21 1887.15,1154.89 P2.33@1949.99,1154.89
GPT1: P2.17 R11.2 | length 62.2
  Top Layer w6: P2.17@2049.99,1554.89 2111.81,1554.89 R11.2@2112.06,1554.65
HFXT_N: C21.1 U1.7 Y2.3 | length 234.6
  Top Layer w6.17: Y2.3@879.7,1312.34 C21.1@916.2,1312.34 916.2,1336.38 908.43,1344.16 908.43,1374.23 975.15,1440.95 U1.7@1013.79,1440.95
HFXT_P: C20.2 R54.2 Y2.1 | length 166.8
  Top Layer w6.17: Y2.1@836.27,1371.21 836.27,1414.24 836.32,1414.3 836.32,1424.99 840.75,1429.42 873.5,1429.42 889.33,1413.59 924.42,1413.59 ; 924.07,1413.59 R54.2@935.73,1425.25
I2C0_CLK: P1.9 R102.1 U1.11 | length 1147
  Top Layer w6: v1(471.49,1023.56) 567.21,1023.56 571.18,1027.54 571.18,1340.18 v1(572.07,1341.07) 570.83,1342.31 570.83,1373.97 R102.1@569.59,1375.21 ; v1(985.46,1376.97) 986.1,1377.6 1013.43,1377.6 U1.11@1013.79,1377.96
  Bottom Layer w6: P1.9@249.99,1054.89 287.5,1017.38 463.14,1017.38 469.32,1023.56 v1(471.49,1023.56) ; v1(572.07,1341.07) 589.96,1341.07 594.32,1345.42 937.85,1345.42 969.4,1376.97 v1(985.46,1376.97)
I2C0_DATA: P1.10 R103.1 U1.12 | length 1150
  Top Layer w6: v1(467.05,1001.08) 567.71,1001.08 582.58,1015.94 582.58,1132.85 581.18,1134.25 581.18,1145.84 582.58,1147.24 582.58,1313.88 v1(598.64,1329.94) 599.42,1330.73 599.42,1370.34 R103.1@600.2,1371.12 ; v1(994.04,1358.9) 997.35,1362.21 U1.12@1013.79,1362.21
  Bottom Layer w6: P1.10@249.99,954.89 296.17,1001.08 v1(467.05,1001.08) ; v1(598.64,1329.94) 598.7,1330 799.73,1330 804.09,1334.35 940.93,1334.35 965.47,1358.9 v1(994.04,1358.9)
I2C1_CLK: J15.2 P1.6 R14.1 R100.1 | length 1933.1
  Top Layer w6: P1.6@249.99,1354.89 296.94,1354.89 345.86,1403.82 414.47,1403.82 432.02,1421.37 432.02,1477.92 495.74,1541.64 500.59,1541.64 v1(554.04,1595.09) ; J15.2@783.15,2026.76 853.25,1956.67 R100.1@853.25,1881.11 ; R100.1@853.01,1881.11 853.79,1881.11 859.06,1875.84 859.06,1874.76 861.5,1872.33 861.5,1787.05 v1(853.25,1778.8) ; v1(1491.29,1509.83) 1494.7,1513.24 R14.1@1508.38,1513.24
  Bottom Layer w6: v1(554.04,1595.09) 646.17,1687.22 646.17,1697.91 727.06,1778.8 v1(853.25,1778.8) 870.02,1795.58 1268.14,1795.58 1415.05,1648.67 1415.05,1586.78 1467.41,1534.42 1487.77,1534.42 1491.29,1530.9 v1(1491.29,1509.83)
I2C1_DATA: J18.1 P1.5 R66.1 R101.1 | length 1885
  Top Layer w6: J18.1@642.46,2026.58 727.01,1942.04 737.77,1942.04 819.84,1859.97 819.84,1824.95 821.02,1823.77 821.02,1821.44 826.29,1816.17 R101.1@827.08,1816.17 ; v1(830.52,1793.84) R101.1@830.52,1816.17 ; v1@1489.72,1550.58 1495.07,1555.93 1495.07,1557.28 R66.1@1508.18,1557.28
  Bottom Layer w6: P1.5@249.99,1454.89 293.75,1498.65 361.92,1498.65 657.11,1793.84 v1(830.52,1793.84) 847.98,1793.84 866.18,1812.04 1287.41,1812.04 1425.05,1674.4 1425.05,1590.92 1469.08,1546.89 1488.19,1546.89 v1(1489.72,1548.42)
I2C_CLK_SENS: J15.1 U8.1 U9.12 | length 783.5
  Top Layer w6.17: U9.12@681.59,1527.77 684.15,1527.77 713.01,1556.63 713.01,1770.17 771.24,1828.4 771.24,1838.54 U8.1@772.64,1839.94 798.17,1839.94 v1(799.49,1841.26) ; J15.1@783.15,2126.76 878.01,2031.9 v1(878.01,1840.24)
  Bottom Layer w6.17: v1(799.49,1841.26) 876.98,1841.26 v1(878.01,1840.24)
I2C_DATA_SENS: J18.2 U8.6 U9.2 | length 671.7
  Top Layer w6.17: U9.2@659.34,1550.01 659.34,1807.36 691.93,1839.94 U8.6@714.38,1839.94 721.66,1839.94 728.35,1846.64 729.36,1846.64 737.43,1854.71 v1(737.43,1922.58)
  Bottom Layer w6.17: J18.2@642.46,2126.58 742.75,2026.3 742.75,1926.2 739.13,1922.58 v1(737.43,1922.58)
I2S_BCLK/MCLK: P1.28 R20.2 | length 1972.8
  Top Layer w6: P1.28@349.99,1154.89 407.18,1154.89 v1(418.52,1143.55) ; v1(660.21,1129.62) 659.78,1129.19 659.78,1051.48 715.88,995.37 715.88,961.17 742.62,934.43 742.62,861.82 888.36,716.08 v1(1031.76,716.08) ; v1(1466.14,719.47) 1492.42,719.47 1531.9,758.95 v1(1531.9,828.2) ; R20.2@1514.83,1202.58 1514.83,1198.08 1526.79,1186.12 1526.79,1017.65 1532.01,1012.43 1533.78,1014.21 v1(1535.89,1014.21)
  Bottom Layer w6: v1(418.52,1143.55) 419.62,1144.64 530.77,1144.64 545.79,1129.62 v1(660.21,1129.62) ; v1(1031.76,716.08) 1180.32,716.08 1203.74,692.66 1350.97,692.66 1377.78,719.47 v1(1466.14,719.47) ; v1(1531.9,828.2) 1530.46,829.64 1530.46,948.03 1535.89,953.46 v1(1535.89,1014.21) v1@1537.42,1012.68
I2S_DATA0: P1.29 R23.2 | length 57.1
  Top Layer w6: P1.29@349.99,1054.89 407.01,1054.89 R23.2@407.09,1054.98
I2S_DATA1: P1.30 R26.2 R27.1 U1.13 | length 1084.3
  Top Layer w6: P1.30@349.99,954.89 415.52,954.89 R26.2@416.16,954.26 416.16,949.76 420.66,945.26 425.16,945.26 435.16,935.26 641.21,935.26 v1(676.29,970.34) ; v1(754.84,949.99) 821.86,949.99 831.66,940.19 924.41,940.19 R27.1@955.92,971.7 ; R27.1@956.7,971.7 R27.1@955.92,971.7 ; U1.13@1013.79,1346.46 1003.94,1346.46 985.24,1327.76 985.24,1326.38 929.04,1270.18 929.04,1011.3 950.65,989.7 950.65,976.97 R27.1@955.92,971.7
  Bottom Layer w6: v1(676.29,970.34) 734.49,970.34 v1(754.84,949.99)
I2S_WCLK: P1.27 R17.2 | length 61
  Top Layer w6: P1.27@349.99,1254.89 390.76,1254.89 391.03,1254.63 R17.2@410.89,1254.63
LFXT_N: C7.1 U1.50 Y1.2 | length 191.7
  Top Layer w7: U1.50@1137.72,1564.88 1137.89,1565.05 1137.89,1589.32 1187.73,1639.16 1187.73,1657.54 1203.83,1673.64 Y1.2@1203.83,1683.48 ; C7.1@1204.34,1731.05 1204.48,1730.91 Y1.2@1204.48,1685.39
LFXT_P: C6.1 R5.1 U1.51 Y1.1 | length 228.5
  Top Layer w7: U1.51@1122.05,1564.97 1122.05,1589.04 1173.58,1640.57 1173.58,1660.75 1161.14,1673.19 1160.61,1673.19 Y1.1@1160.61,1683.56 ; C6.1@1160.4,1733.28 1160.52,1733.4 1160.52,1768 R5.1@1160.64,1768.12 ; Y1.1@1161.18,1685.39 C6.1@1161.18,1733.28
LOGGER: P2.34 R1.2 R3.1 U1.38 | length 1833
  Top Layer w6: U1.38@1277.57,1472.45 1358.93,1472.45 1378.34,1491.86 1394.45,1491.86 1454.86,1552.26 v1(1454.86,1586.82) ; v1(1820.09,1367.94) 1820.09,1389.43 1829.29,1398.64 1829.29,1417.96 v1(1543.46,1703.79) 1543.46,1705.95 1535.15,1714.27 1535.15,1896.22 1893.52,2254.59 R3.1@1914.33,2254.59 ; P2.34@1949.99,1254.89 1981.62,1286.53 v1(1981.62,1308.46)
  Bottom Layer w6: v1(1454.86,1586.82) 1454.86,1615.18 v1(1543.46,1703.79) ; v1(1820.09,1367.94) 1879.57,1308.46 v1(1981.62,1308.46)
LP_GPIO3: R15.1 R74.1 R78.1 | length 1429
  Top Layer w6: R15.1@456.19,1355.07 456.19,1350.57 476.82,1329.94 476.82,1061.79 v1(496.34,1042.26) ; v1(741.22,726.7) 902,565.92 1218.65,565.92 1232.03,579.31 R78.1@1261.8,579.31 1261.8,666.22 R74.1@1263.88,668.3
  Bottom Layer w6: v1(496.34,1042.26) 496.34,994.46 680.94,809.86 680.94,787.86 741.22,727.58 v1(741.22,726.7)
LP_GPIO4: R6.2 R12.1 R50.1 R70.1 | length 3398.8
  Top Layer w6: R12.1@454.15,1454.73 454.15,1452.21 507.31,1452.21 510.83,1448.7 510.83,1060.14 v1(524.35,1046.61) ; v1(1212.9,867.22) 1214.43,865.69 1214.43,862.16 1235.64,840.95 R50.1@1236.43,840.95 R50.1@1238.73,843.26 ; R50.1@1236.43,843.28 1238.73,843.28 R70.1@1238.73,897.26 ; v1(1400.26,867.22) 1413.86,880.82 v1(1413.86,1009.76) ; v1(1493.06,975.33) 1516.88,975.33 1526.71,965.5 v1(1560.32,965.5) ; v1(1778.43,1692.53) 1965.41,1692.53 1987.5,1670.43 1987.5,1635.01 1985,1632.51 1985,1572.93 1987.5,1570.43 1987.5,1564.33 2013,1538.83 2013,1475.38 2012.47,1474.85 2012.47,1439.36 2039.81,1412.02 2060.16,1412.02 2087.5,1384.68 2087.5,1239.36 2040.6,1192.46 2014.36,1192.46 v1(1997.82,1175.93) ; v1(1779.38,1755.95) 1809.16,1755.95 R6.2@1810.52,1754.59 ; v1(1987.31,994.73) 1987.5,994.92 1987.5,1071.88 v1(2001.2,1085.57)
  Bottom Layer w6: v1(524.35,1046.61) 525.89,1045.08 525.89,1014.97 661.22,879.63 698.84,879.63 711.24,867.22 v1(1212.9,867.22) v1(1400.26,867.22) ; v1(1413.86,1009.76) 1458.63,1009.76 v1(1493.06,975.33) ; v1(1560.32,965.5) 1593.98,999.16 1871.67,999.16 1883.23,987.6 1929.64,987.6 1936.78,994.73 v1(1987.31,994.73) ; v1(1778.43,1692.53) 1778.43,1755.01 v1(1779.38,1755.95) ; v1(1997.82,1175.93) 2001.2,1172.56 v1(2001.2,1085.57)
LP_GPIO5: R10.1 R13.2 R75.1 R79.1 | length 3582.7
  Top Layer w6: R10.1@451.54,1553.55 487.31,1553.55 v1(489.05,1555.29) ; v1(534.85,1349.05) 534.85,1057.76 v1(552.36,1040.24) ; v1(1522.31,723.1) 1522.78,722.63 1522.78,663.21 v1(1607.31,578.68) 1608.12,579.49 R79.1@1632.36,579.49 1632.36,580.28 1642.52,590.44 R75.1@1642.52,666.76 ; v1(1835.87,875.44) 2037.72,875.44 2185.04,1022.76 v1(2185.04,1267.38) ; R13.2@1846.57,1456.82 1846.57,1452.32 1863.79,1435.1 1863.79,1431.95 v1(1865.32,1430.42)
  Bottom Layer w6: v1(489.05,1555.29) 520.8,1523.54 520.8,1363.09 v1(534.85,1349.05) ; v1(552.36,1040.24) 703.94,888.67 1450.34,888.67 1505.1,833.9 1505.1,800.22 1522.78,782.54 1522.78,723.58 v1(1522.31,723.1) ; v1(1607.31,578.68) 1694.25,578.68 1745.46,629.89 1779.8,629.89 1835.87,685.97 v1(1835.87,875.44) ; v1(1865.32,1430.42) 1893.34,1402.41 2069.67,1402.41 2185.04,1287.03 v1(2185.04,1267.38)
LP_GPIO5_Buf: J6.3 R73.2 R79.2 | length 329.3
  Top Layer w6: R79.2@1632.36,552.72 R79.2@1632.36,553.5 1659.74,553.5 R73.2@1661.27,551.98 1722.51,551.98 1748.18,526.31 v1(1764.42,526.31)
  Bottom Layer w6: v1(1764.42,526.31) 1879.81,526.31 1923.3,569.8 J6.3@1923.3,578.12
LP_GPIO6: R7.1 R18.2 R52.1 R71.1 | length 3274.3
  Top Layer w6: R7.1@451.02,1653.17 524.08,1653.17 527.59,1649.66 527.59,1625.79 v1(531.22,1622.17) ; v1(553.68,1074.4) v1(553.68,1345.01) ; v1(1499.31,909.98) 1577.7,909.98 1590.79,896.89 1590.79,844.55 1588.26,842.02 v1(1588.26,839.86) 1610.13,839.86 R52.1@1612.48,842.21 1613.32,843.04 1613.32,908.7 R71.1@1613.79,909.18 ; v1@1845.74,909.63 v1(1844.65,908.54) 2056.68,908.54 2161.08,1012.94 v1(2161.08,1227.39) ; R18.2@1847.6,1362.41 1848.14,1362.95 1848.14,1401.99 v1(1848.69,1402.54)
  Bottom Layer w6: v1(531.22,1622.17) 531.22,1621.49 538.05,1614.65 538.05,1491.55 553.68,1475.93 v1(553.68,1345.01) ; v1(553.68,1074.4) 553.68,1072.49 727.49,898.67 1006.39,898.67 1030.47,922.75 1287.52,922.75 1301.49,908.78 1498.11,908.78 v1(1499.31,909.98) ; v1(1588.26,839.86) 1775.97,839.86 v1(1844.65,908.54) ; v1(1848.69,1402.54) 1867.03,1402.54 1877.15,1392.41 2065.52,1392.41 2161.08,1296.85 v1(2161.08,1227.39)
LP_GPIO6_Buf: J4.3 R44.2 R71.2 | length 479.7
  Top Layer w6: R71.2@1608.52,929.11 1613.79,934.38 R71.2@1613.79,935.16 1678.58,935.16 R44.2@1680.17,936.75 1680.17,935.96 1689.31,926.82 1691.33,926.82 1784.48,833.67 1784.48,579.06 J4.3@1782.8,577.38
LP_RESET: J9.3 P2.16 | length 2371.4
  Top Layer w6: v1(707.37,2321.16) 707.67,2320.87 707.67,2264.94 J9.3@707.96,2264.64 ; v1(1563.05,2323.91) 1563.65,2324.52 1841.61,2324.52 1927.8,2324.52 1933.14,2319.17 1933.14,2035.5 1948.73,2019.92 1948.73,1964.59 1988.14,1925.18 2122.96,1925.18 2126.48,1921.67 2126.48,1569.63 2126.56,1569.55 2126.56,1524.74 2118.59,1516.76 2118.59,1471.96 2110.69,1464.07 2059.16,1464.07 P2.16@2049.99,1454.89
  Bottom Layer w6: v1(707.37,2321.16) 710.11,2323.91 v1(1563.05,2323.91)
NetC4_2: C4.2 J13.2 R39.2 U2.14 U2.15 | length 1084.1
  Top Layer w10: v1(627.64,647.77) 627.64,648.86 629.49,650.7 R39.2@629.49,673.93
  Bottom Layer w10: v1(627.64,647.77) 702.33,647.77 706.6,652.04
  Bottom Layer w40: J13.2@132.3,353.09 132.3,461.52 155.74,484.95 311.7,484.95 311.7,617.06 407.96,713.32 645.32,713.32 706.6,652.04 v4(767.87,590.77)
NetC5_2: C5.2 J14.2 R49.2 U2.11 U2.12 | length 816.9
  Top Layer w10: v1(626.61,478.94) 627.38,478.17 627.38,455.94 R49.2@628.68,454.64
  Bottom Layer w10: v1(626.61,478.94) 710.22,478.94 711.4,477.76
  Bottom Layer w40: J14.2@239.78,153.23 246.53,153.23 307.94,214.63 382.4,214.63 466.98,299.2 570.2,299.2 711.4,440.41 711.4,477.76 v4@766.95,533.31
  other v4: 766.33,531.92
NetC8_2: C8.2 J1.1 J2.1 | length 232.7
  Top Layer w6: J1.1@1310.72,2023.3 J1.1@1311.55,2024.13
  Top Layer w7: J1.1@1309.68,2023.73 cw(c1309.68,2022.26) J1.1@1310.72,2023.3
  Top Layer w10.25: C8.2@1079.34,2023.73 C8.2@1079.39,2023.77 1079.43,2023.73 J1.1@1309.68,2023.73
NetC9_1: C9.1 C10.1 L1.2 | length 393.7
  Top Layer w10.25: C9.1@1053.38,2049.83 1053.12,2050.09 1053.12,2443.03 L1.2@1053.36,2443.28
NetC19_1: C19.1 J12.1 J12.2 J12.3 J12.4 R108.1 | length 772
  Top Layer w15: R108.1@2038.18,28.69 2038.97,28.69 2040.88,26.77 J12.1@2106.31,26.77 ; C19.1@2105.89,426.07 2106.1,425.86 2106.1,367.14 J12.2@2106.31,366.93
  Bottom Layer w15: J12.3@2255.91,26.77 J12.1@2106.31,26.77 J12.2@2106.31,366.93 2169.97,366.93 2175.34,372.3 2250.54,372.3 J12.4@2255.91,366.93
NetC38_1: C38.1 R55.1 U6.8 | length 135.3
  Top Layer w10: C38.1@795.75,967.29 796.12,967.29 801.39,972.56 801.39,984.56 ; U6.8@801.39,1008.35 801.39,984.56 ; R55.1@881.8,962.94 881.8,966.88 864.12,984.56 801.39,984.56
NetC41_1: C41.1 R62.1 U8.5 | length 113.3
  Top Layer w6: C41.1@639.21,1918.75 639.21,1895.47 643.71,1895.47 679.55,1859.63 U8.5@714.38,1859.63
NetD1_1: D1.1 J5.1 | length 305.7
  Top Layer w40: D1.1@756.82,311.85 756.82,313.87 800.47,357.52 v4@806.31,357.52
  Bottom Layer w40: v4@806.31,357.52 915.62,357.52 J5.1@1005.26,447.16
  other v4: 808.23,358.33
NetD2_1: D2.1 R35.1 | length 218.2
  Top Layer w6: D2.1@289.27,2409.85 379.31,2319.81 R35.1@470.21,2319.81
